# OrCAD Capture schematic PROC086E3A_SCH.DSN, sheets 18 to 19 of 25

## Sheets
18 21. JAMR3 INTERFACE: size C; title: JAMR3 INTERFACE
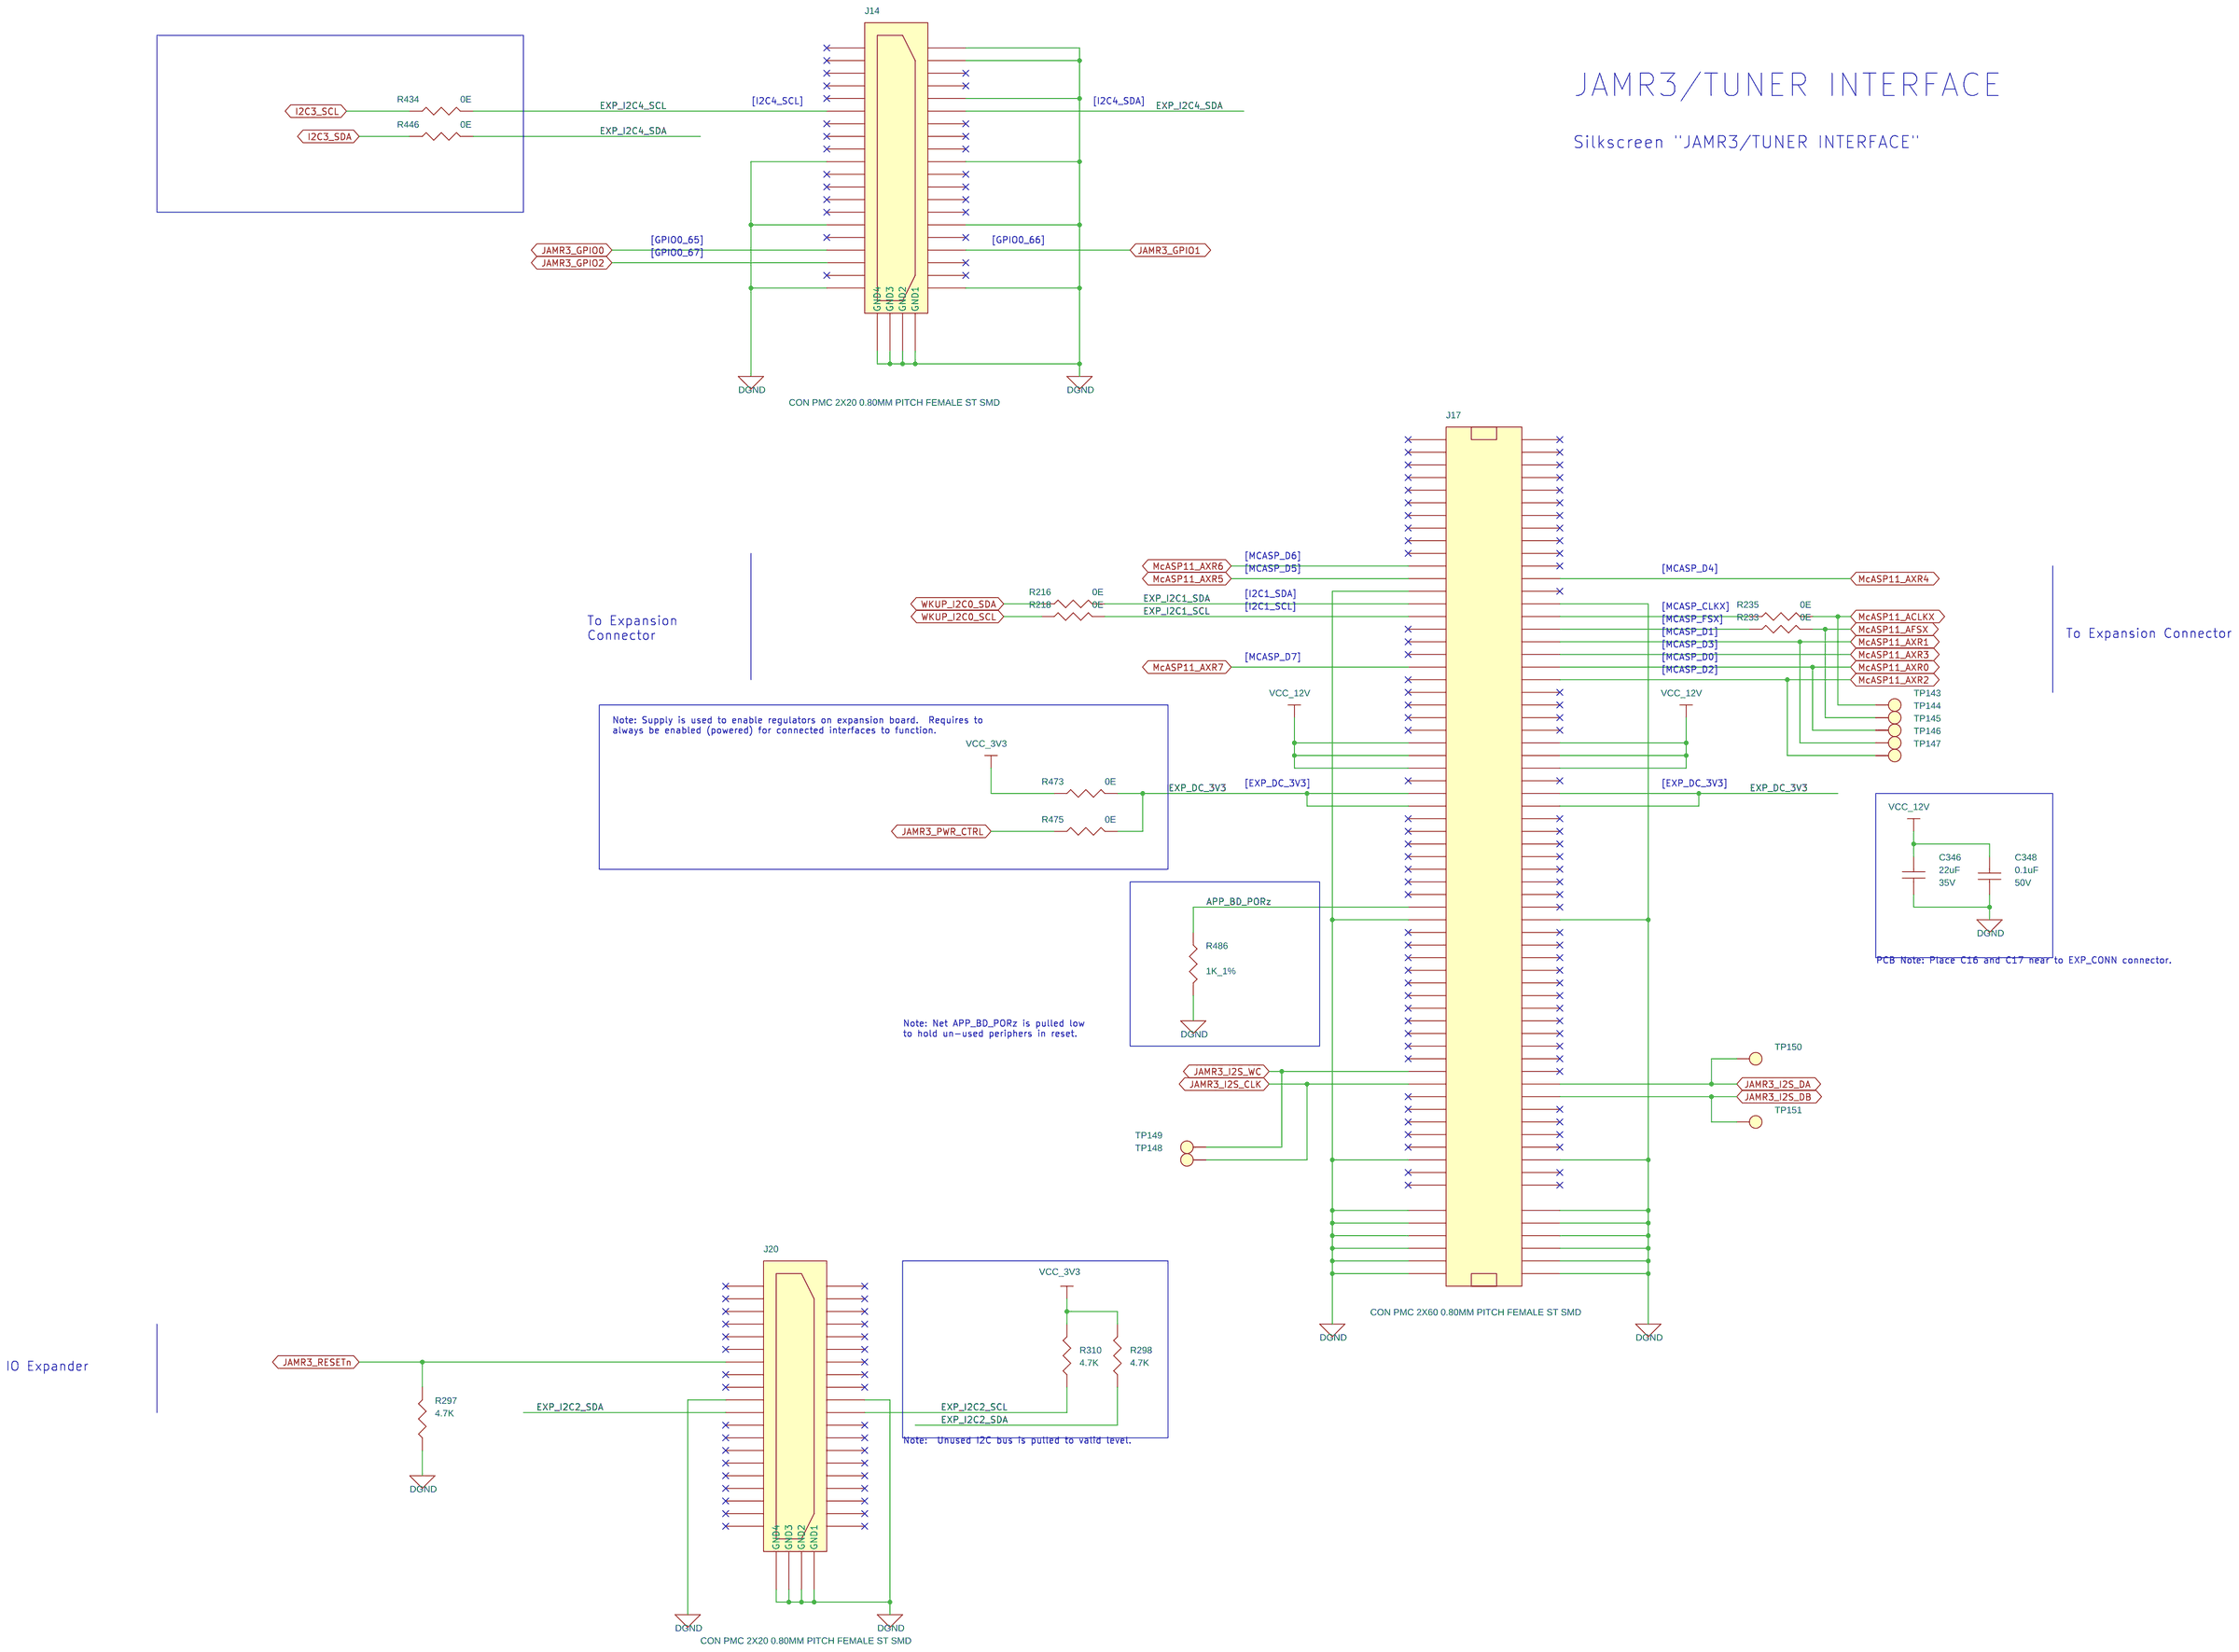
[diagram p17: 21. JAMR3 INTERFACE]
19 22. DIR INTERFACE: size C; title: DIR INTERFACE
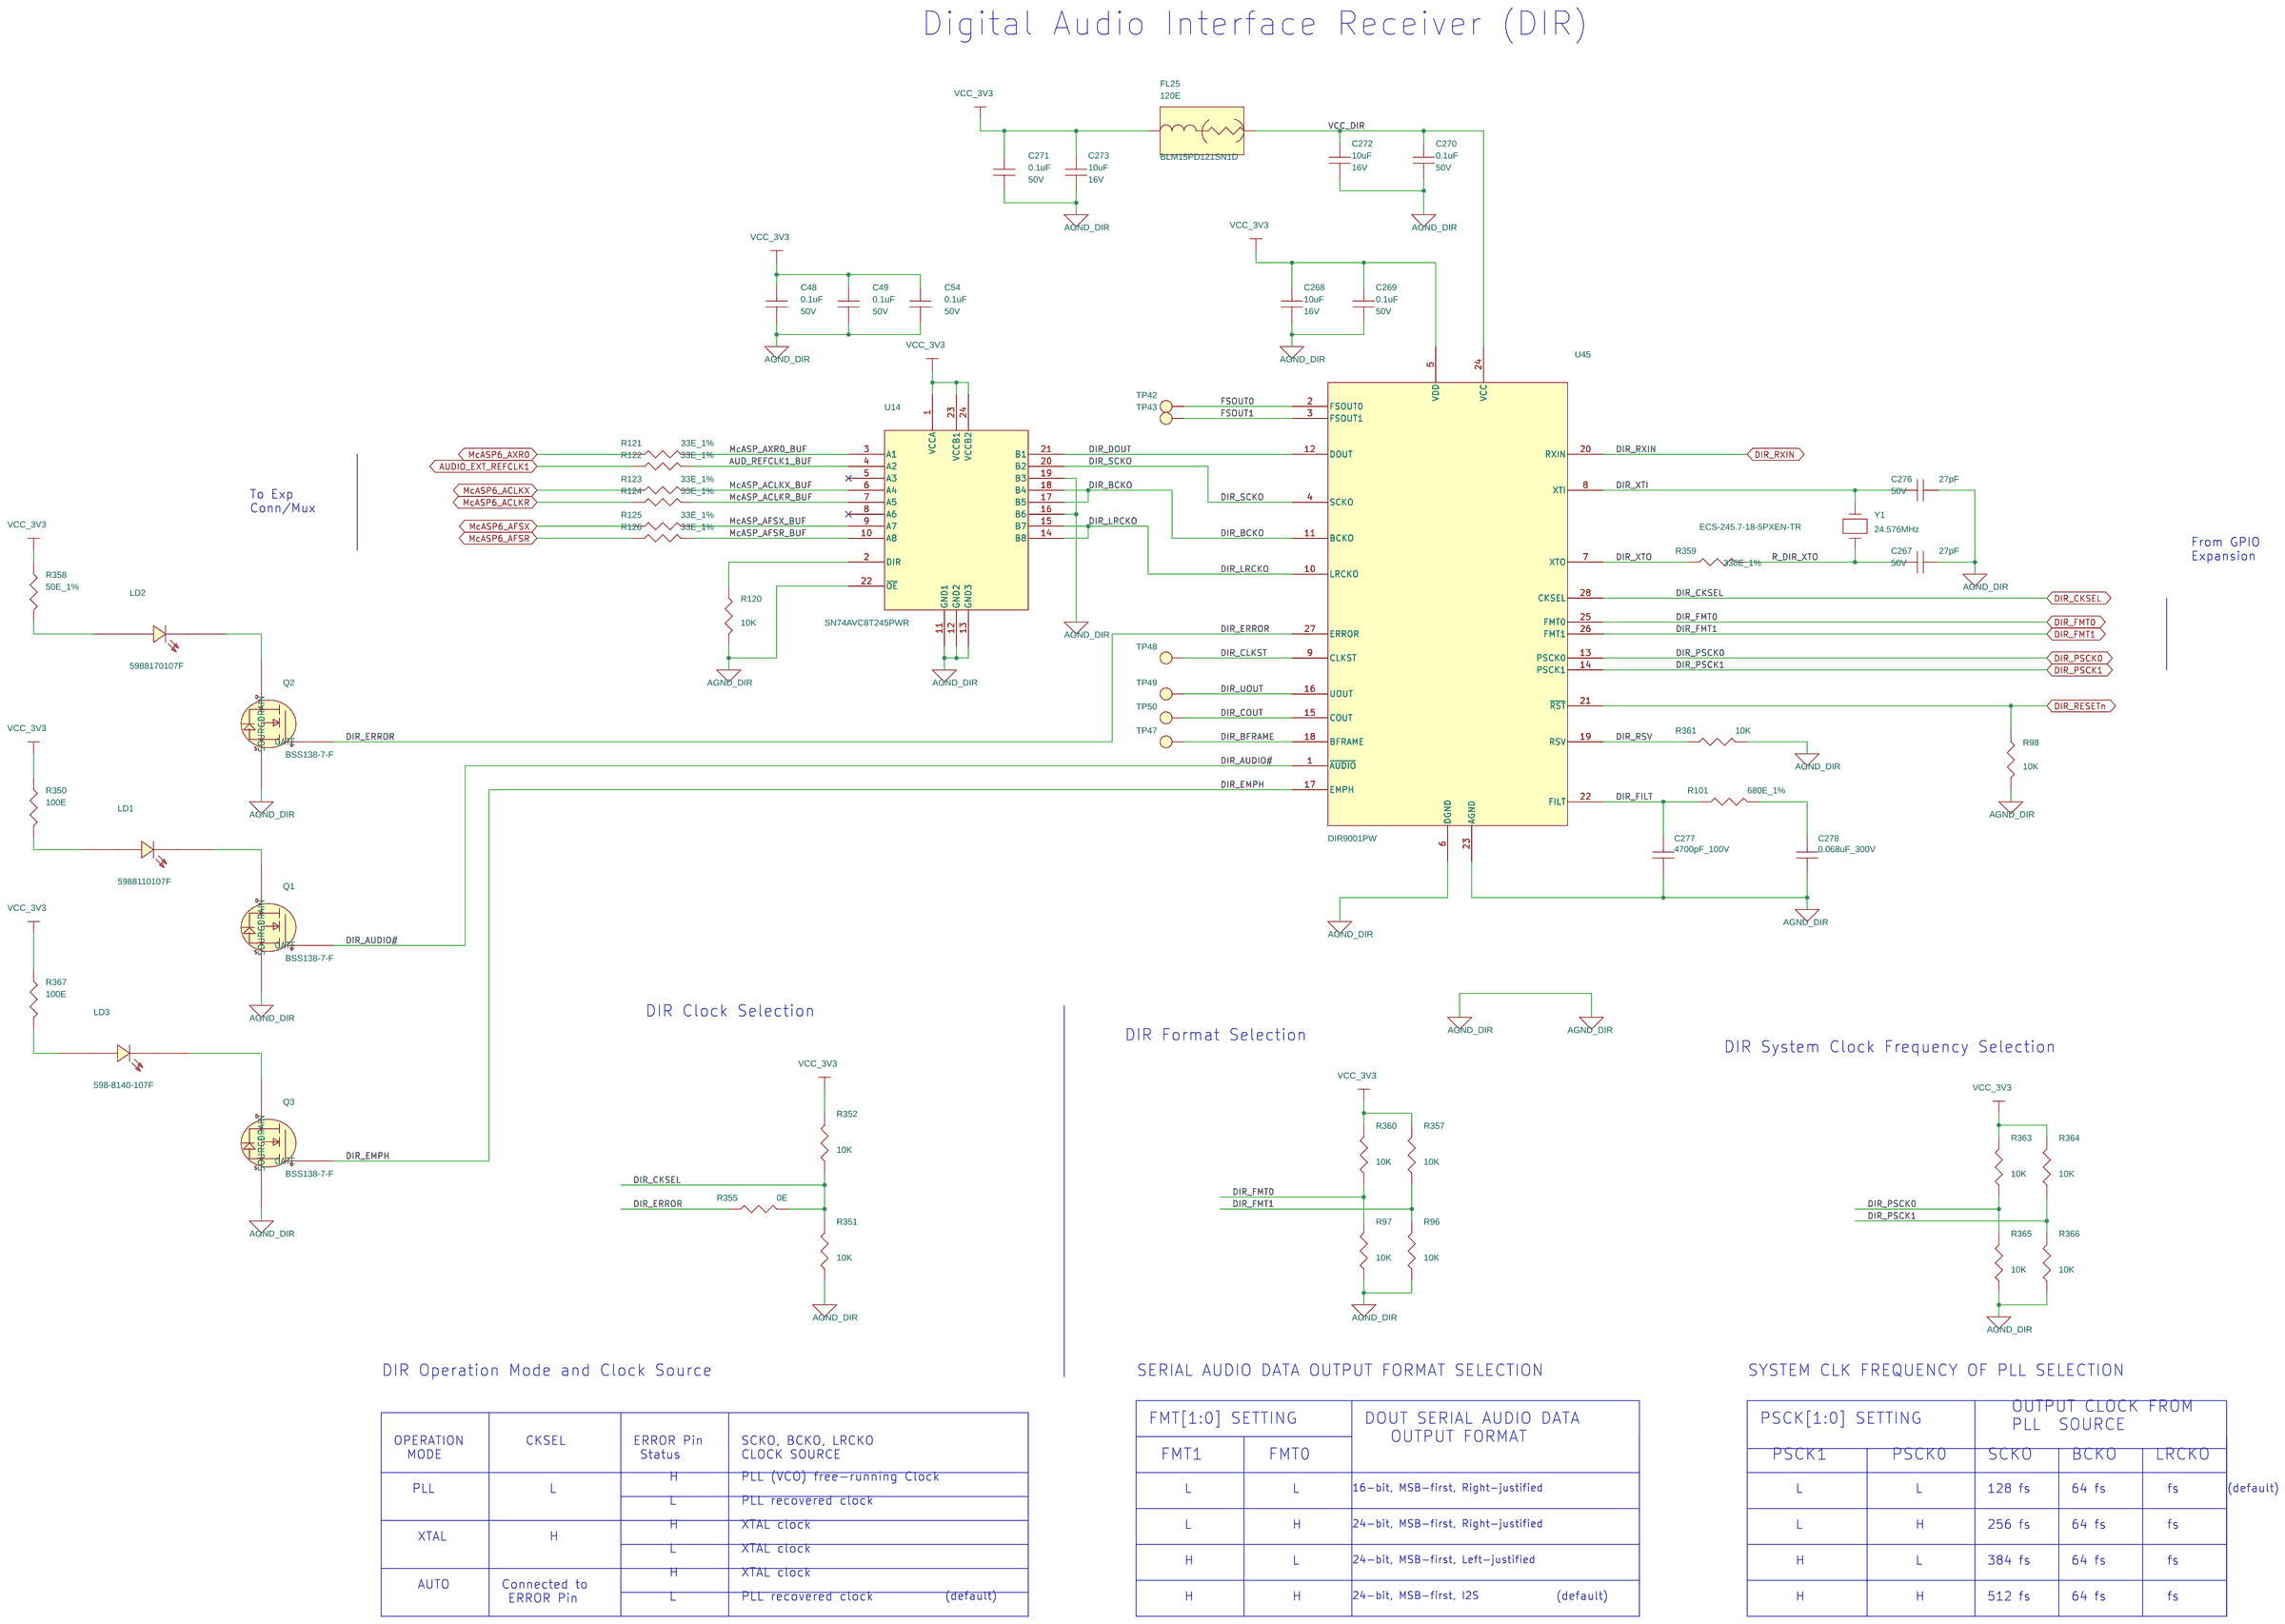
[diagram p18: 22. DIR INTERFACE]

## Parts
sheet 21. JAMR3 INTERFACE
C346  22uF  [CAP1206_2]
C348  0.1uF  [CAP0402_0-75]
J14  CON_PMC_2X20_F  [CON_PMC2X20_QSE-020-01-D-A_S_S_S_3-4]
J17  CON_PMC_2X60_F  [CON_PMC2X60_QSE-060-01-D-A_S_S_S_3-4]
J20  CON_PMC_2X20_F  [CON_PMC2X20_QSE-020-01-D-A_S_S_S_3-4]
R216  0E  [RES0402_0-5]
R218  0E  [RES0402_0-5]
R233  0E  [RES0402_0-5]
R235  0E  [RES0402_0-5]
R297  4.7K  [RES0402_0-5]
R298  4.7K  [RES0402_0-5]
R310  4.7K  [RES0402_0-5]
R434  0E  [RES0402_0-5]
R446  0E  [RES0402_0-5]
R473  0E  [RES0402_0-5]
R475  0E  [RES0402_0-5]
R486  1K_1%  [RES0402_0-5]
TP143  TP20_SMD  [TP20_SMD]
TP144  TP20_SMD  [TP20_SMD]
TP145  TP20_SMD  [TP20_SMD]
TP146  TP20_SMD  [TP20_SMD]
TP147  TP20_SMD  [TP20_SMD]
TP148  TP20_SMD  [TP20_SMD]
TP149  TP20_SMD  [TP20_SMD]
TP150  TP20_SMD  [TP20_SMD]
TP151  TP20_SMD  [TP20_SMD]
sheet 22. DIR INTERFACE
C48  0.1uF  [CAP0402_0-75]
C49  0.1uF  [CAP0402_0-75]
C54  0.1uF  [CAP0402_0-75]
C267  27pF  [CAP0402_0-75]
C268  10uF  [CAP0603_1]
C269  0.1uF  [CAP0402_0-75]
C270  0.1uF  [CAP0402_0-75]
C271  0.1uF  [CAP0402_0-75]
C272  10uF  [CAP0603_1]
C273  10uF  [CAP0603_1]
C276  27pF  [CAP0402_0-75]
C277  4700pF_100V  [CAP_196-85_280X100_TH_6-5]
C278  0.068uF_300V  [CAP_393-7_510X180_TH_10-5]
FL25  120E  [EMIFIL_BLM15A_0402_0-6]
LD1  5988110107F  [LED_0805]
LD2  5988170107F  [LED_0805_0-7]
LD3  598-8140-107F  [LED_0805]
Q1  BSS138-7-F  [SOT23-123_1-1]
Q2  BSS138-7-F  [SOT23-123_1-1]
Q3  BSS138-7-F  [SOT23-123_1-1]
R96  10K  [RES0402_0-5]
R97  10K  [RES0402_0-5]
R98  10K  [RES0402_0-5]
R101  680E_1%  [RES0603_0-75]
R120  10K  [RES0402_0-5]
R121  33E_1%  [RES0402_0-5]
R122  33E_1%  [RES0402_0-5]
R123  33E_1%  [RES0402_0-5]
R124  33E_1%  [RES0402_0-5]
R125  33E_1%  [RES0402_0-5]
R126  33E_1%  [RES0402_0-5]
R350  100E  [RES0402_0-5]
R351  10K  [RES0402_0-5]
R352  10K  [RES0402_0-5]
R355  0E  [RES0402_0-5]
R357  10K  [RES0402_0-5]
R358  50E_1%  [RES0402_0-75]
R359  330E_1%  [RES0402_0-5]
R360  10K  [RES0402_0-5]
R361  10K  [RES0402_0-5]
R363  10K  [RES0402_0-5]
R364  10K  [RES0402_0-5]
R365  10K  [RES0402_0-5]
R366  10K  [RES0402_0-5]
R367  100E  [RES0402_0-5]
TP42  TP40_SMD  [TP40_SMD]
TP43  TP40_SMD  [TP40_SMD]
TP47  TP40_SMD  [TP40_SMD]
TP48  TP40_SMD  [TP40_SMD]
TP49  TP40_SMD  [TP40_SMD]
TP50  TP40_SMD  [TP40_SMD]
U14  SN74AVC8T245PWR  [TSSOP24_25-59_315X180_1-2]
U45  DIR9001PW  [TSSOP28_25-59_390X180_1-2]
Y1  24.576MHz  [XTAL_CSM-7X_450X190_SMD_4-3]

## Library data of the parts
C346 = CAP: CAP CERAMIC 22uF 35V 20% X5R 1206; Chkd/date: MANIRAJA/130318; Crtd /date: MANIRAJA/130318; Custom_Duty: 15%; Customs_HS_Code: 85322990; Distributor_name: DIGIKEY; Distributor_part_number: 445-8045-1-ND; Footprint Path: Y:\MIS_DATABASE\Library\ALTIUM_TOOL\PCB_FOOTPRINTS\Altium_Footprint_Lib.PcbLib; Height: 1.80MM; Library Path: Y:\MIS_DATABASE\Library\ALTIUM_TOOL\SCHEMATICS_PARTS\MS_DISCRETE_Library.schlib; Mfr_name: TDK CORPORATION; Mfr_part_number: C3216X5R1V226M160AC; Mistral Part No: 120018030003-R; Package: 1206; Part_type: CAPACITORS\CERAMIC; Project: TI_SVB_MAXWELL_VPS; RoHS: RoHS; Temperature: -55°C+85°C; Tolerance: 20%; Voltage: 35V; Wattage: NA; Weight: 16.2mg; Datasheet: Y:\MIS_DATABASE\DATASHEETS\CAPACITORS\C3216X5R1V226M160AC.PDF
C48 C49 C54 C269-C271 C348 = CAP: CAP CERAMIC 0.1uF 50V 10% X7R 0402; Chkd/date: VASANTHA/281216; Crtd /date: CHAITHANYA/051011; Custom_Duty: 15%; Customs_HS_Code: 85322990; Distributor_name: DIGIKEY; Distributor_part_number: 445-173610-1-ND; Footprint Path: Y:\MIS_DATABASE\Library\ALTIUM_TOOL\PCB_FOOTPRINTS\Altium_Footprint_Lib.PcbLib; Height: 0.60MM; Library Path: Y:\MIS_DATABASE\Library\ALTIUM_TOOL\SCHEMATICS_PARTS\MS_DISCRETE_Library.schlib; Mfr_name: TDK CORPORATION; Mfr_part_number: C1005X7R1H104K050BE; Mistral Part No: 120011100014-R; Package: 0402; Part_type: CAPACITORS\CERAMIC; Project: VP-4000-BASE-BOARD; RoHS: RoHS; Temperature: -55°C+125°C; Tolerance: 10%; Voltage: 50V; Wattage: NA; Weight: 0.65mg; Datasheet: Y:\MIS_DATABASE\DATASHEETS\CAPACITORS\TDK_C-SER_FEB19.PDF
J14 J20 = CON_PMC_20X2_F: CON PMC 2X20 0.80MM PITCH FEMALE ST SMD; Chkd/date: MANIRAJA/190718; Crtd /date: ALVY/190718; Custom_Duty: 24%; Customs_HS_Code: 85369090; Distributor_name: DIGIKEY; Distributor_part_number: SAM10642-ND; Footprint Path: Y:\MIS_DATABASE\Library\ALTIUM_TOOL\PCB_FOOTPRINTS\Altium_Footprint_Lib.PcbLib; Height: 3.33MM; Library Path: Y:\MIS_DATABASE\Library\ALTIUM_TOOL\SCHEMATICS_PARTS\MS_CONNECTOR_Library.schlib; Mfr_name: SAMTEC; Mfr_part_number: QSE-020-01-L-D-A-K; Mistral Part No: 150018070032-R; Package: SMD; Part_type: CONNECTOR\PMC; Project: TI_J7ES_EVM_TUNER_EXP; RoHS: RoHS; Temperature: -55°C+125°C; Tolerance: NA; Voltage: NA; Wattage: NA; Weight: NA; Datasheet: Y:\MIS_DATABASE\DATASHEETS\CONNECTORS\QSE3.PDF
J17 = CON_PMC_60X2_F_QSH-060: CON PMC 2X60 0.80MM PITCH FEMALE ST SMD; Chkd/date: MANIRAJA/190718; Crtd /date: MAZHAR/131009; Custom_Duty: 24%; Customs_HS_Code: 85369090; Distributor_name: DIGIKEY; Distributor_part_number: SAM10646-ND; Footprint Path: Y:\MIS_DATABASE\Library\ALTIUM_TOOL\PCB_FOOTPRINTS\Altium_Footprint_Lib.PcbLib; Height: 3.33MM; Library Path: Y:\MIS_DATABASE\Library\ALTIUM_TOOL\SCHEMATICS_PARTS\MS_CONNECTOR_Library.schlib; Mfr_name: SAMTEC; Mfr_part_number: QSE-060-01-L-D-A; Mistral Part No: 150009100010-R; Package: SMD; Part_type: CONNECTOR\PMC; Project: NPOL_FPS; RoHS: RoHS; Temperature: -55°C+125°C; Tolerance: NA; Voltage: NA; Wattage: NA; Weight: NA; Datasheet: Y:\MIS_DATABASE\DATASHEETS\CONNECTORS\QSE3.PDF
R216 R218 R233 R235 R355 R434 R446 R473 = RESISTOR: RES 0E 1/10W JUMPER 0402; Chkd/date: VASANTHA/061216; Crtd /date: NAVEED/201014; Custom_Duty: 15%; Customs_HS_Code: 85332119; Distributor_name: DIGIKEY; Distributor_part_number: P0.0JCT-ND; Footprint Path: Y:\MIS_DATABASE\Library\ALTIUM_TOOL\PCB_FOOTPRINTS\Altium_Footprint_Lib.PcbLib; Height: 0.40MM; IBISSP_MODLES: VALUE REPEATING 2 TIME; Library Path: Y:\MIS_DATABASE\Library\ALTIUM_TOOL\SCHEMATICS_PARTS\MS_DISCRETE_Library.schlib; Mfr_name: PANASONIC-ECG; Mfr_part_number: ERJ-2GE0R00X; Mistral Part No: 110018030052-R; Package: 0402; Part_type: RESISTORS\FIXED; Project: AEGIS POM; RoHS: RoHS; Temperature: -55°C+155°C; Tolerance: NA; Voltage: NA; Wattage: 1/10W; Weight: 0.8mg; Datasheet: Y:\MIS_DATABASE\DATASHEETS\RESISTORS\PAN-ERJSER_NOV17.PDF
R297 R298 R310 = RESISTOR: RES 4.7K 1/16W 5% 0402; Chkd/date: VASANTHA/281216; Crtd /date: BAVISH/010611; Custom_Duty: 15%; Customs_HS_Code: 85332119; Distributor_name: DIGIKEY; Distributor_part_number: 541-4.7KJCT-ND; Footprint Path: Y:\MIS_DATABASE\Library\ALTIUM_TOOL\PCB_FOOTPRINTS\Altium_Footprint_Lib.PcbLib; Height: 0.40MM; Library Path: Y:\MIS_DATABASE\Library\ALTIUM_TOOL\SCHEMATICS_PARTS\MS_DISCRETE_Library.schlib; Mfr_name: VISHAY; Mfr_part_number: CRCW04024K70JNED; Mistral Part No: 110011060001-R; Package: 0402; Part_type: RESISTORS\FIXED; Project: AM4515_EVM_LCD; RoHS: RoHS; Temperature: -55°C+155°C; Tolerance: 5%; Voltage: NA; Wattage: 1/16W; Weight: 0.65mg; Datasheet: Y:\MIS_DATABASE\DATASHEETS\RESISTORS\CRCW0603.PDF
R475 = RESISTOR: RES 0E 1/10W JUMPER 0402; Assembly_Instruction: DNI; Chkd/date: VASANTHA/061216; Crtd /date: NAVEED/201014; Custom_Duty: 15%; Customs_HS_Code: 85332119; Distributor_name: DIGIKEY; Distributor_part_number: P0.0JCT-ND; Footprint Path: Y:\MIS_DATABASE\Library\ALTIUM_TOOL\PCB_FOOTPRINTS\Altium_Footprint_Lib.PcbLib; Height: 0.40MM; IBISSP_MODLES: VALUE REPEATING 2 TIME; Library Path: Y:\MIS_DATABASE\Library\ALTIUM_TOOL\SCHEMATICS_PARTS\MS_DISCRETE_Library.schlib; Mfr_name: PANASONIC-ECG; Mfr_part_number: ERJ-2GE0R00X; Mistral Part No: 110018030052-R; Package: 0402; Part_type: RESISTORS\FIXED; Project: AEGIS POM; RoHS: RoHS; Temperature: -55°C+155°C; Tolerance: NA; Voltage: NA; Wattage: 1/10W; Weight: 0.8mg; Datasheet: Y:\MIS_DATABASE\DATASHEETS\RESISTORS\PAN-ERJSER_NOV17.PDF
R486 = RESISTOR: RES 1K 1/10W 1% 0402; Chkd/date: VASANTHA/281216; Crtd /date: MAZHAR/150506; Custom_Duty: 15%; Customs_HS_Code: 85332119; Distributor_name: DIGIKEY; Distributor_part_number: P1.00KLCT-ND; Footprint Path: Y:\MIS_DATABASE\Library\ALTIUM_TOOL\PCB_FOOTPRINTS\Altium_Footprint_Lib.PcbLib; Height: 0.40MM; Library Path: Y:\MIS_DATABASE\Library\ALTIUM_TOOL\SCHEMATICS_PARTS\MS_DISCRETE_Library.schlib; Mfr_name: PANASONIC-ECG; Mfr_part_number: ERJ-2RKF1001X; Mistral Part No: 110009030411-R; Package: 0402; Part_type: RESISTORS\FIXED; Project: VOCERA; RoHS: RoHS; Temperature: -55°C+155°C; Tolerance: 1%; Voltage: NA; Wattage: 1/10W; Weight: 0.8mg; Datasheet: Y:\MIS_DATABASE\DATASHEETS\RESISTORS\PAN-ERJSER_NOV17.PDF
TP143-TP151 = TESTPOINT: TESTPOINT CIR 20 SMD; Chkd/date: SHREESHAIL/171006; Crtd /date: MAZHAR/171006; Custom_Duty: NA; Customs_HS_Code: NA; Distributor_name: NA; Distributor_part_number: NA; Footprint Path: Y:\MIS_DATABASE\Library\ALTIUM_TOOL\PCB_FOOTPRINTS\Altium_Footprint_Lib.PcbLib; Height: NA; Library Path: Y:\MIS_DATABASE\Library\ALTIUM_TOOL\SCHEMATICS_PARTS\MS_DISCRETE_Library.schlib; MECHANICAL 3D STEP FILE: NA; Mfr_name: LOCAL; Mistral Part No: NA; Package: SMD; Project: BT MODULE_CSRBC04; RoHS: NA; Temperature: NA; Tolerance: NA; Voltage: NA; Wattage: NA; Weight: NA; Datasheet: NA
C267 C276 = CAP: CAP CERAMIC 27pF 50V 5% C0G(NP0) 0402; Chkd/date: MANIRAJA/130917; Crtd /date: MANIRAJA/130917; Custom_Duty: 15%; Customs_HS_Code: 85322990; Distributor_name: DIGIKEY; Distributor_part_number: 478-1075-1-ND; Footprint Path: Y:\MIS_DATABASE\Library\ALTIUM_TOOL\PCB_FOOTPRINTS\Altium_Footprint_Lib.PcbLib; Height: 0.56MM; Library Path: Y:\MIS_DATABASE\Library\ALTIUM_TOOL\SCHEMATICS_PARTS\MS_DISCRETE_Library.schlib; Mfr_name: AVX CORPORATION; Mfr_part_number: 04025A270JAT2A; Mistral Part No: 120014100024-R; Package: 0402; Part_type: CAPACITORS\CERAMIC; Project: TI_SVB_MAXWELL_DUT; RoHS: RoHS; Temperature: -55°C+125°C; Tolerance: 5%; Voltage: 50V; Wattage: NA; Weight: 0.65mg; Datasheet: Y:\MIS_DATABASE\DATASHEETS\CAPACITORS\AVX_MLC.PDF
C268 C272 C273 = CAP: CAP CERAMIC 10uF 16V 20% X6S 0603; Chkd/date: VASANTHA/170117; Crtd /date: VASANTHA/170117; Custom_Duty: 15%; Customs_HS_Code: 85322990; Distributor_name: DIGIKEY; Distributor_part_number: 490-7198-1-ND; Footprint Path: Y:\MIS_DATABASE\Library\ALTIUM_TOOL\PCB_FOOTPRINTS\Altium_Footprint_Lib.PcbLib; Height: 0.90MM; Library Path: Y:\MIS_DATABASE\Library\ALTIUM_TOOL\SCHEMATICS_PARTS\MS_DISCRETE_Library.schlib; Mfr_name: MURATA; Mfr_part_number: GRM188C81C106MA73D; Mistral Part No: 120017010004-R; Package: 0603; Part_type: CAPACITORS\CERAMIC; Project: TRMM_SMART-M_PS; RoHS: RoHS; Temperature: -55°C+105°C; Tolerance: 20%; Voltage: 16V; Wattage: NA; Weight: 6.3mg; Datasheet: Y:\MIS_DATABASE\DATASHEETS\CAPACITORS\MURATA-GXX-SER_NOV17.PDF
C277 = CAP: CAP POLYPROPYLENE 4700pF 100V 5% TH; Chkd/date: NAVEED/270315; Crtd /date: JEBRAN/260215; Custom_Duty: 15%; Customs_HS_Code: 85322990; Distributor_name: MOUSER; Distributor_part_number: 80-PHE426DJ4470JR05; Footprint Path: Y:\MIS_DATABASE\Library\ALTIUM_TOOL\PCB_FOOTPRINTS\Altium_Footprint_Lib.PcbLib; Height: 6.50MM; Library Path: Y:\MIS_DATABASE\Library\ALTIUM_TOOL\SCHEMATICS_PARTS\MS_DISCRETE_Library.schlib; Mfr_name: KEMET; Mfr_part_number: PHE426DJ4470JR05; Mistral Part No: 120015020004-R; Package: THRU-HOLE; Part_type: CAPACITORS\POLYPROPYLENE; Project: GALILEO_DAUGHTER_CARD; RoHS: RoHS; Temperature: -55°C+105°C; Tolerance: 5%; Voltage: 100V; Wattage: NA; Weight: 172.44mg; Datasheet: Y:\MIS_DATABASE\DATASHEETS\CAPACITORS\PHE426-SERIES.PDF
C278 = CAP: CAP POLYPROPYLENE 0.068uF 300V 5% TH; Chkd/date: NAVEED/260315; Crtd /date: JEBRAN/250315; Custom_Duty: 15%; Customs_HS_Code: 85322990; Distributor_name: MOUSER; Distributor_part_number: 80-PHE426JA5680JR05; Footprint Path: Y:\MIS_DATABASE\Library\ALTIUM_TOOL\PCB_FOOTPRINTS\Altium_Footprint_Lib.PcbLib; Height: 10.50MM; Library Path: Y:\MIS_DATABASE\Library\ALTIUM_TOOL\SCHEMATICS_PARTS\MS_DISCRETE_Library.schlib; Mfr_name: KEMET; Mfr_part_number: PHE426JA5680JR05; Mistral Part No: 120015030004-R; Package: THRU-HOLE; Part_type: CAPACITORS\POLYPROPYLENE; Project: GALILEO_DAUGHTER_CARD; RoHS: RoHS; Temperature: -55°C+105°C; Tolerance: 5%; Voltage: 300V; Wattage: NA; Weight: NA; Datasheet: Y:\MIS_DATABASE\DATASHEETS\CAPACITORS\PHE426-SERIES.PDF
FL25 = EMIFILTER_IND: IND FERRITE BEAD CHIP 120E 1.3A 0402; Chkd/date: VASANTHA/010117; Crtd /date: CHAITHANYA/150312; Custom_Duty: 24%; Customs_HS_Code: 85437099; Distributor_name: DIGIKEY; Distributor_part_number: 490-5203-1-ND; Footprint Path: Y:\MIS_DATABASE\Library\ALTIUM_TOOL\PCB_FOOTPRINTS\Altium_Footprint_Lib.PcbLib; Height: 0.55MM; Library Path: Y:\MIS_DATABASE\Library\ALTIUM_TOOL\SCHEMATICS_PARTS\MS_FILTER_Library.schlib; Mfr_name: MURATA; Mfr_part_number: BLM15PD121SN1D; Mistral Part No: 130012030043-R; Package: 0402; Part_type: FILTER; Project: GEN_3-8; RoHS: RoHS; Temperature: -55°C+125°C; Tolerance: 25%; Voltage: NA; Wattage: NA; Weight: 0.65mg; Datasheet: Y:\MIS_DATABASE\DATASHEETS\DISCRETES\INDUCTORS\BLM15X-SER.PDF
LD1 = LED_598-8170-107F: LED ALINGAP RED CLEAR 0805 SMD; Chkd/date: BALACHANDAR/160514; Crtd /date: SARANYA/070514; Custom_Duty: 24%; Customs_HS_Code: 85437099; Distributor_name: DIGIKEY; Distributor_part_number: 350-2038-1-ND; Footprint Path: Y:\MIS_DATABASE\Library\ALTIUM_TOOL\PCB_FOOTPRINTS\Altium_Footprint_Lib.PcbLib; Height: 0.70MM; Mfr_name: DIALIGHT; Mistral Part No: 130014050069-R; Package: 0805; Part_type: OPTO\LED; Project: AEGIS GP BETA2; RoHS: RoHS; Temperature: NA; Tolerance: NA; Voltage: NA; Wattage: NA; Weight: NA; Datasheet: Y:\MIS_DATABASE\DATASHEETS\DISCRETES\LEDS\598-SER.PDF
LD2 = LED_598-8170-107F: LED ALINGAP GREEN CLEAR 0805; Chkd/date: MANIRAJA/230817; Crtd /date: SARANYA/070514; Custom_Duty: 24%; Customs_HS_Code: 85437099; Distributor_name: DIGIKEY; Distributor_part_number: 350-2044-1-ND; Footprint Path: Y:\MIS_DATABASE\Library\ALTIUM_TOOL\PCB_FOOTPRINTS\Altium_Footprint_Lib.PcbLib; Height: 0.70MM; Mfr_name: DIALIGHT; Mistral Part No: 130014050065-R; Package: 0805; Part_type: OPTO\LED; Project: AEGIS GP BETA2; RoHS: RoHS; Temperature: -30°C+85°C; Tolerance: NA; Voltage: NA; Wattage: NA; Weight: NA; Datasheet: Y:\MIS_DATABASE\DATASHEETS\DISCRETES\LEDS\598-SER.PDF
LD3 = LED_598-8170-107F: LED ALINGAP YELLOW CLEAR 0805 SMD; Chkd/date: BALACHANDAR/160514; Crtd /date: SARANYA/070514; Custom_Duty: 24%; Customs_HS_Code: 85437099; Distributor_name: DIGIKEY; Distributor_part_number: 350-2041-1-ND; Height: 0.70MM; Mfr_name: DIALIGHT; Mistral Part No: 130014050066-R; Package: 0805; Part_type: OPTO\LED; Project: AEGIS GP BETA2; RoHS: RoHS; Temperature: NA; Tolerance: NA; Voltage: NA; Wattage: NA; Weight: NA; Datasheet: Y:\MIS_DATABASE\DATASHEETS\DISCRETES\LEDS\598-SER.PDF
Q1-Q3 = MOSFET_2N7002_SOT23: IC MOSFET N-CHANNEL 50V 200mA SOT23-123; Chkd/date: MANIRAJA/190618; Crtd /date: USMAN/240709; Custom_Duty: 15%; Customs_HS_Code: 85423100; Distributor_name: DIGIKEY; Distributor_part_number: BSS138-FDICT-ND; Footprint Path: Y:\MIS_DATABASE\Library\ALTIUM_TOOL\PCB_FOOTPRINTS\Altium_Footprint_Lib.PcbLib; Height: 1.10MM; Library Path: Y:\MIS_DATABASE\Library\ALTIUM_TOOL\SCHEMATICS_PARTS\MS_MOSFET_Library.schlib; Mfr_name: DIODES INC; Mistral Part No: 142009070019-R; Package: SOT23-123; Part_type: ICS\POWER\MOSFET; Project: KHAN_MAIN; RoHS: RoHS; Temperature: -55°C+150°C; Tolerance: NA; Voltage: 50V; Wattage: 300mW; Weight: 8mg; Datasheet: Y:\MIS_DATABASE\DATASHEETS\DISCRETES\TRANSISTORS_FETS\BSS138.PDF
R96 R97 R351 R363 R364 = RESISTOR: RES 10K 1/16W 5% 0402; Assembly_Instruction: DNI; Chkd/date: VASANTHA/061216; Crtd /date: MAZHAR/230805; Custom_Duty: 15%; Customs_HS_Code: 85332119; Distributor_name: DIGIKEY; Distributor_part_number: 311-10KJRCT-ND; Footprint Path: Y:\MIS_DATABASE\Library\ALTIUM_TOOL\PCB_FOOTPRINTS\Altium_Footprint_Lib.PcbLib; Height: 0.40MM; Library Path: Y:\MIS_DATABASE\Library\ALTIUM_TOOL\SCHEMATICS_PARTS\MS_DISCRETE_Library.schlib; Mfr_name: YAGEO AMERICA; Mfr_part_number: RC0402JR-0710KL; Mistral Part No: 110011060021-R; Package: 0402; Part_type: RESISTORS\FIXED; Project: HSE; RoHS: RoHS; Temperature: -55°C+155°C; Tolerance: 5%; Voltage: NA; Wattage: 1/16W; Weight: 0.65mg; Datasheet: Y:\MIS_DATABASE\DATASHEETS\RESISTORS\RCXXXXL-SER_MAR18.PDF
R98 R120 R352 R357 R360 R361 R365 R366 = RESISTOR: RES 10K 1/16W 5% 0402; Chkd/date: VASANTHA/061216; Crtd /date: MAZHAR/230805; Custom_Duty: 15%; Customs_HS_Code: 85332119; Distributor_name: DIGIKEY; Distributor_part_number: 311-10KJRCT-ND; Footprint Path: Y:\MIS_DATABASE\Library\ALTIUM_TOOL\PCB_FOOTPRINTS\Altium_Footprint_Lib.PcbLib; Height: 0.40MM; Library Path: Y:\MIS_DATABASE\Library\ALTIUM_TOOL\SCHEMATICS_PARTS\MS_DISCRETE_Library.schlib; Mfr_name: YAGEO AMERICA; Mfr_part_number: RC0402JR-0710KL; Mistral Part No: 110011060021-R; Package: 0402; Part_type: RESISTORS\FIXED; Project: HSE; RoHS: RoHS; Temperature: -55°C+155°C; Tolerance: 5%; Voltage: NA; Wattage: 1/16W; Weight: 0.65mg; Datasheet: Y:\MIS_DATABASE\DATASHEETS\RESISTORS\RCXXXXL-SER_MAR18.PDF
R101 = RESISTOR: RES 680E 1/10W 1% 0603; Chkd/date: NAVEED/201014; Crtd /date: VASANTHA/110914; Custom_Duty: 15%; Customs_HS_Code: 85332119; Distributor_name: DIGIKEY; Distributor_part_number: 311-680HRCT-ND; Footprint Path: Y:\MIS_DATABASE\Library\ALTIUM_TOOL\PCB_FOOTPRINTS\Altium_Footprint_Lib.PcbLib; Height: 0.55MM; Library Path: Y:\MIS_DATABASE\Library\ALTIUM_TOOL\SCHEMATICS_PARTS\MS_DISCRETE_Library.schlib; Mfr_name: YAGEO AMERICA; Mfr_part_number: RC0603FR-07680RL; Mistral Part No: 110014090002-R; Package: 0603; Part_type: RESISTORS\FIXED; Project: PDDS; RoHS: RoHS; Temperature: -55°C+155°C; Tolerance: 1%; Voltage: NA; Wattage: 1/10W; Weight: 2mg; Datasheet: Y:\MIS_DATABASE\DATASHEETS\RESISTORS\RCXXXXL-SER_MAR18.PDF
R121-R126 = RESISTOR: RES 33E 1/10W 1% 0402; Chkd/date: VASANTHA/061216; Crtd /date: JEBRAN/171114; Custom_Duty: 15%; Customs_HS_Code: 85332119; Distributor_name: DIGIKEY; Distributor_part_number: P33.0LCT-ND; Footprint Path: Y:\MIS_DATABASE\Library\ALTIUM_TOOL\PCB_FOOTPRINTS\Altium_Footprint_Lib.PcbLib; Height: 0.40MM; Library Path: Y:\MIS_DATABASE\Library\ALTIUM_TOOL\SCHEMATICS_PARTS\MS_DISCRETE_Library.schlib; Mfr_name: PANASONIC-ECG; Mfr_part_number: ERJ-2RKF33R0X; Mistral Part No: 110014110006-R; Package: 0402; Part_type: RESISTORS\FIXED; Project: ZK BIOMETRIC; RoHS: RoHS; Temperature: -55°C+155°C; Tolerance: 1%; Voltage: NA; Wattage: 1/10W; Weight: 0.8mg; Datasheet: Y:\MIS_DATABASE\DATASHEETS\RESISTORS\PAN-ERJSER_NOV17.PDF
R350 R367 = RESISTOR: RES 100E 1/16W 5% 0402; Chkd/date: MANIRAJA/230817; Crtd /date: MANIRAJA/230817; Custom_Duty: 15%; Customs_HS_Code: 85332119; Distributor_name: DIGIKEY; Distributor_part_number: 541-100JCT-ND; Footprint Path: Y:\MIS_DATABASE\Library\ALTIUM_TOOL\PCB_FOOTPRINTS\Altium_Footprint_Lib.PcbLib; Height: 0.40MM; Library Path: Y:\MIS_DATABASE\Library\ALTIUM_TOOL\SCHEMATICS_PARTS\MS_DISCRETE_Library.schlib; Mfr_name: VISHAY; Mfr_part_number: CRCW0402100RJNED; Mistral Part No: 110014060039-R; Package: 0402; Part_type: RESISTORS\FIXED; Project: TI_MAXIE_CPB; RoHS: RoHS; Temperature: -55°C+155°C; Tolerance: 5%; Voltage: NA; Wattage: 1/16W; Weight: 0.65mg; Datasheet: Y:\MIS_DATABASE\DATASHEETS\RESISTORS\CRCW0603.PDF
R358 = RESISTOR: RES 50E 1/8W 1% 0402; Chkd/date: MANIRAJA/160218; Crtd /date: ALVY/140218; Custom_Duty: 15%; Customs_HS_Code: 85332119; Distributor_name: DIGIKEY; Distributor_part_number: 1284-1326-1-ND; Footprint Path: Y:\MIS_DATABASE\Library\ALTIUM_TOOL\PCB_FOOTPRINTS\Altium_Footprint_Lib.PcbLib; Height: 0.60MM; Library Path: Y:\MIS_DATABASE\Library\ALTIUM_TOOL\SCHEMATICS_PARTS\MS_DISCRETE_Library.schlib; Mfr_name: ATC; Mfr_part_number: 504L50R0FTNCFT; Mistral Part No: 110018020017-R; Package: 0402; Part_type: RESISTORS\FIXED; Project: TI_SVB_MAXWELL_SPM; RoHS: RoHS; Temperature: -40°C+125°C; Tolerance: 1%; Voltage: NA; Wattage: 1/8W; Weight: 0.65mg; Datasheet: Y:\MIS_DATABASE\DATASHEETS\RESISTORS\ATC504L-SERIES.PDF
R359 = RESISTOR: RES 330E 1/16W 1% 0402; Chkd/date: VASANTHA/201216; Crtd /date: GEETHA/090606; Custom_Duty: 15%; Customs_HS_Code: 85332119; Distributor_name: DIGIKEY; Distributor_part_number: 311-330LRCT-ND; Footprint Path: Y:\MIS_DATABASE\Library\ALTIUM_TOOL\PCB_FOOTPRINTS\Altium_Footprint_Lib.PcbLib; Height: 0.40MM; Library Path: Y:\MIS_DATABASE\Library\ALTIUM_TOOL\SCHEMATICS_PARTS\MS_DISCRETE_Library.schlib; Mfr_name: YAGEO AMERICA; Mfr_part_number: RC0402FR-07330RL; Mistral Part No: 110009030691-R; Package: 0402; Part_type: RESISTORS\FIXED; Project: PNAV; RoHS: RoHS; Temperature: -55°C+155°C; Tolerance: 1%; Voltage: NA; Wattage: 1/16W; Weight: 0.65mg; Datasheet: Y:\MIS_DATABASE\DATASHEETS\RESISTORS\RCXXXXL-SER_MAR18.PDF
TP42 TP43 TP47-TP50 = TESTPOINT: TESTPOINT CIR 40 SMD; Chkd/date: MAZHAR/190505; Crtd /date: MAZHAR/190505; Distributor_name: NA; Distributor_part_number: NA; Footprint Path: Y:\MIS_DATABASE\Library\ALTIUM_TOOL\PCB_FOOTPRINTS\Altium_Footprint_Lib.PcbLib; Height: NA; Library Path: Y:\MIS_DATABASE\Library\ALTIUM_TOOL\SCHEMATICS_PARTS\MS_DISCRETE_Library.schlib; MECHANICAL 3D STEP FILE: NA; Mfr_name: LOCAL; Mistral Part No: 130009030933; Package: SMD; Project: RAINIER-3; RoHS: NA; Temperature: NA; Tolerance: NA; Voltage: NA; Wattage: NA; Weight: NA; Datasheet: NA
U14 = SN74AVC8T245PWR_TSSOP24: IC 8-BIT DUAL-SUPPLY BUS TRANSCEIVER TSSOP24; Chkd/date: MANIRAJA/040917; Crtd /date: USMAN/040509; Custom_Duty: 15%; Customs_HS_Code: 85423100; Distributor_name: DIGIKEY; Distributor_part_number: 296-19100-1-ND; Height: 1.20MM; Mfr_name: TEXAS INSTRUMENTS; Mistral Part No: 143009060004-R; Package: TSSOP24; Part_type: ICS\TELECOM\TRANSCEIVER; Project: STORM2; RoHS: RoHS; Temperature: -40°C+85°C; Tolerance: NA; Voltage: NA; Wattage: NA; Weight: 89.5mg; Datasheet: Y:\MIS_DATABASE\DATASHEETS\ICS\DIGITAL\BUSTRANSCEIVER\SN74AVC8T245.PDF
U45 = DIR9001PW_TSSOP28_TI: IC 24-BIT AUDIO INTERFACE RECEIVER TSSOP28; Chkd/date: NAVEED/240315; Crtd /date: VASANTHA/250914; Custom_Duty: 15%; Customs_HS_Code: 85423100; Distributor_name: DIGIKEY; Distributor_part_number: 296-21389-5-ND; Footprint Path: Y:\MIS_DATABASE\Library\ALTIUM_TOOL\PCB_FOOTPRINTS\Altium_Footprint_Lib.PcbLib; Height: 1.20MM; Library Path: Y:\MIS_DATABASE\Library\ALTIUM_TOOL\SCHEMATICS_PARTS\MS_BUSDRIVERTRANSCEIVER_Library.schlib; Library Ref: DIR9001PW_TSSOP28; Mfr_name: TEXAS INSTRUMENTS; Mistral Part No: 141014090026-R; Package: TSSOP28; Part_type: ICS\DIGITAL\BUSTRANSCEIVER; Project: GALILEO_EVM; RoHS: RoHS; Temperature: -40°C+85°C; Tolerance: NA; Voltage: NA; Wattage: NA; Weight: NA; Datasheet: Y:\MIS_DATABASE\DATASHEETS\ICS\DIGITAL\BUSTRANSCEIVER\DIR9001.PDF
Y1 = CRY: CRY 24.576MHz 18pF SMD; Chkd/date: MANIRAJA/041018; Crtd /date: MUDDU/190710; Custom_Duty: 24%; Customs_HS_Code: 85439000; Distributor_name: DIGIKEY; Distributor_part_number: XC1703CT-ND; Footprint Path: Y:\MIS_DATABASE\Library\ALTIUM_TOOL\PCB_FOOTPRINTS\Altium_Footprint_Lib.PcbLib; Height: 4.30MM; Library Path: Y:\MIS_DATABASE\Library\ALTIUM_TOOL\SCHEMATICS_PARTS\MS_DISCRETE_Library.schlib; Mfr_name: ECS INC; Mfr_part_number: ECS-245.7-18-5PXEN-TR; Mistral Part No: 130010070011-R; Package: SMD; Part_type: CRYSTAL; Project: TTCU; RoHS: RoHS; Temperature: -40°C+85°C; Tolerance: NA; Voltage: NA; Wattage: NA; Weight: NA; Datasheet: Y:\MIS_DATABASE\DATASHEETS\MISC\CRY_OSC\CSM-7X.PDF

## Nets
DGND: C48.2 C49.2 C54.2 C267.2 C268.2 C269.2 C270.2 C271.2 C272.2 C273.2 C276.2 C277.2 C278.2 C346.2 C348.1 J14.2 J14.4 J14.10 J14.19 J14.20 J14.29 J14.30 J14.39 J14.40 J14.41(GND1) J14.42(GND2) J14.43(GND3) J14.44(GND4) J17.26 J17.27 J17.77 J17.78 J17.115 J17.116 J17.121 J17.122 J17.123 J17.124 J17.125 J17.126 J17.127 J17.128 J17.129 J17.130 J17.131 J17.132 J20.19 J20.20 J20.41(GND1) J20.42(GND2) J20.43(GND3) J20.44(GND4) Q1.2(SOURCE) Q2.2(SOURCE) Q3.2(SOURCE) R96.1 R97.1 R98.1 R120.1 R297.2 R351.1 R361.2 R365.1 R366.1 R486.2 U14.11(GND1) U14.12(GND2) U14.13(GND3) U14.16(B6) U14.19(B3) U14.22(~{OE}) U45.6(DGND) U45.23(AGND) ; also on sheet 5 6 7 8 9 10 11 12 13 14 15 16 17 20 21 22 23 25
VCC_3V3: C48.1 C49.1 C54.1 C268.1 C269.1 C271.1 C273.1 FL25.1 R298.1 R310.1 R350.1 R352.2 R357.2 R358.1 R360.2 R363.2 R364.2 R367.1 R473.1 U14.1(VCCA) U14.23(VCCB1) U14.24(VCCB2) U45.5(VDD) ; also on sheet 5 14 15 16 17 20 21 22 23 25
VCC_12V: C346.1 C348.2 J17.49 J17.50 J17.51 J17.52 J17.53 J17.54 ; also on sheet 5 16 20
VCC_DIR: C270.1 C272.1 FL25.2 U45.24(VCC)
APP_BD_PORz: J17.76 R486.1
AUD_REFCLK1_BUF: R122.2 U14.4(A2)
AUDIO_EXT_REFCLK1: R122.1 ; also on sheet 5
DIR_AUDIO#: Q1.1(GATE) U45.1(~{AUDIO})
DIR_BCKO: U14.17(B5) U14.18(B4) U45.11(BCKO)
DIR_BFRAME: TP47.1(TP) U45.18(BFRAME)
DIR_CKSEL: R351.2 R352.1 R355.2 U45.28(CKSEL) ; also on sheet 5
DIR_CLKST: TP48.1(TP) U45.9(CLKST)
DIR_COUT: TP50.1(TP) U45.15(COUT)
DIR_DOUT: U14.21(B1) U45.12(DOUT)
DIR_EMPH: Q3.1(GATE) U45.17(EMPH)
DIR_ERROR: Q2.1(GATE) R355.1 U45.27(ERROR)
DIR_FILT: C277.1 R101.1 U45.22(FILT)
DIR_FMT0: R97.2 R360.1 U45.25(FMT0) ; also on sheet 5
DIR_FMT1: R96.2 R357.1 U45.26(FMT1) ; also on sheet 5
DIR_LRCKO: U14.14(B8) U14.15(B7) U45.10(LRCKO)
DIR_PSCK0: R363.1 R365.2 U45.13(PSCK0) ; also on sheet 5
DIR_PSCK1: R364.1 R366.2 U45.14(PSCK1) ; also on sheet 5
DIR_RESETn: R98.2 U45.21(~{RST}) ; also on sheet 5
DIR_RSV: R361.1 U45.19(RSV)
DIR_RXIN: U45.20(RXIN) ; also on sheet 25
DIR_SCKO: U14.20(B2) U45.4(SCKO)
DIR_UOUT: TP49.1(TP) U45.16(UOUT)
DIR_XTI: C276.1 U45.8(XTI) Y1.1
DIR_XTO: R359.1 U45.7(XTO)
EXP_DC_3V3: J17.57 J17.58 J17.59 J17.60 R473.2 R475.2
EXP_I2C1_SCL: J17.30 R218.2
EXP_I2C1_SDA: J17.28 R216.2
EXP_I2C2_SCL: J20.22 R310.2
EXP_I2C2_SDA: J20.21 R298.2
EXP_I2C4_SCL: J14.11 R434.2
EXP_I2C4_SDA: J14.12 R446.2
FSOUT0: TP42.1(TP) U45.2(FSOUT0)
FSOUT1: TP43.1(TP) U45.3(FSOUT1)
I2C3_SCL: R434.1 ; also on sheet 5 20 22 23
I2C3_SDA: R446.1 ; also on sheet 5 20 22 23
JAMR3_GPIO0: J14.33 ; also on sheet 5
JAMR3_GPIO1: J14.34 ; also on sheet 5
JAMR3_GPIO2: J14.35 ; also on sheet 5
JAMR3_I2S_CLK: J17.104 TP148.1(TP) ; also on sheet 14
JAMR3_I2S_DA: J17.103 TP150.1(TP) ; also on sheet 14
JAMR3_I2S_DB: J17.105 TP151.1(TP) ; also on sheet 5
JAMR3_I2S_WC: J17.102 TP149.1(TP) ; also on sheet 14
JAMR3_PWR_CTRL: R475.1 ; also on sheet 5
JAMR3_RESETn: J20.13 R297.1 ; also on sheet 5
McASP6_ACLKR: R124.1 ; also on sheet 5
McASP6_ACLKX: R123.1 ; also on sheet 14
McASP6_AFSR: R126.1 ; also on sheet 5
McASP6_AFSX: R125.1 ; also on sheet 14
McASP6_AXR0: R121.1 ; also on sheet 14
McASP11_ACLKX: R235.2 TP143.1(TP) ; also on sheet 5
McASP11_AFSX: R233.2 TP144.1(TP) ; also on sheet 5
McASP11_AXR0: J17.37 TP145.1(TP) ; also on sheet 5
McASP11_AXR1: J17.33 TP146.1(TP) ; also on sheet 5
McASP11_AXR2: J17.39 TP147.1(TP) ; also on sheet 5
McASP11_AXR3: J17.35 ; also on sheet 5
McASP11_AXR4: J17.23 ; also on sheet 5
McASP11_AXR5: J17.24 ; also on sheet 5
McASP11_AXR6: J17.22 ; also on sheet 5
McASP11_AXR7: J17.38 ; also on sheet 5
McASP_ACLKR_BUF: R124.2 U14.7(A5)
McASP_ACLKX_BUF: R123.2 U14.6(A4)
McASP_AFSR_BUF: R126.2 U14.10(A8)
McASP_AFSX_BUF: R125.2 U14.9(A7)
McASP_AXR0_BUF: R121.2 U14.3(A1)
R_DIR_XTO: C267.1 R359.2 Y1.2
WKUP_I2C0_SCL: R218.1 ; also on sheet 5
WKUP_I2C0_SDA: R216.1 ; also on sheet 5
N23684707: C278.1 R101.2
N23911217: J17.31 R233.1
N23911219: J17.29 R235.1
N24736802: R120.2 U14.2(DIR)
N24987908: LD2.2 R358.2
N24987961: LD2.1 Q2.3(DRAIN)
N24990777: LD3.2 R367.2
N24990859: LD3.1 Q3.3(DRAIN)
N24990930: LD1.2 R350.2
N24990935: LD1.1 Q1.3(DRAIN)

Not connected (* = marked no-connect by the designer): J14 1* 3* 5* 6* 7* 8* 9* 13* 14* 15* 16* 17* 18* 21* 22* 23* 24* 25* 26* 27* 28* 31* 32* 36* 37* 38*; J17 1* 2* 3* 4* 5* 6* 7* 8* 9* 10* 11* 12* 13* 14* 15* 16* 17* 18* 19* 20* 21* 25* 32* 34* 36* 40* 41* 42* 43* 44* 45* 46* 47* 48* 55* 56* 61* 62* 63* 64* 65* 66* 67* 68* 69* 70* 71* 72* 73* 74* 75* 79* 80* 81* 82* 83* 84* 85* 86* 87* 88* 89* 90* 91* 92* 93* 94* 95* 96* 97* 98* 99* 100* 101* 106* 107* 108* 109* 110* 111* 112* 113* 114* 117* 118* 119* 120*; J20 1* 2* 3* 4* 5* 6* 7* 8* 9* 10* 11* 12* 14* 15* 16* 17* 18* 23* 24* 25* 26* 27* 28* 29* 30* 31* 32* 33* 34* 35* 36* 37* 38* 39* 40*; U14 5(A3)* 8(A6)*

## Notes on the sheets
sheet 18
- JAMR3/TUNER INTERFACE
- [I2C4_SCL]
- [I2C4_SDA]
- Silkscreen "JAMR3/TUNER INTERFACE"
- [GPIO0_65]
- [GPIO0_66]
- [GPIO0_67]
- [MCASP_D6]
- [MCASP_D5]
- [MCASP_D4]
- [I2C1_SDA]
- [I2C1_SCL]
- [MCASP_CLKX]
- To Expansion
  Connector
- [MCASP_D1]
- [MCASP_FSX]
- To Expansion Connector
- [MCASP_D3]
- [MCASP_D7]
- [MCASP_D0]
- [MCASP_D2]
- Note: Supply is used to enable regulators on expansion board.  Requires to
  always be enabled (powered) for connected interfaces to function.
- [EXP_DC_3V3]
- [EXP_DC_3V3]
- PCB Note: Place C16 and C17 near to EXP_CONN connector.
- Note: Net APP_BD_PORz is pulled low
  to hold un-used periphers in reset.
- IO Expander
- Note:  Unused I2C bus is pulled to valid level.
sheet 19
- Digital Audio Interface Receiver (DIR)
- To Exp
  Conn/Mux
- From GPIO
  Expansion
- DIR Clock Selection
- DIR Format Selection
- DIR System Clock Frequency Selection
- DIR Operation Mode and Clock Source
- SERIAL AUDIO DATA OUTPUT FORMAT SELECTION
- SYSTEM CLK FREQUENCY OF PLL SELECTION
- OUTPUT CLOCK FROM
  PLL  SOURCE
- FMT[1:0] SETTING
- DOUT SERIAL AUDIO DATA
     OUTPUT FORMAT
- PSCK[1:0] SETTING
- OPERATION
    MODE
- CKSEL
- ERROR Pin
   Status
- SCKO, BCKO, LRCKO
  CLOCK SOURCE
- FMT1
- FMT0
- PSCK1
- PSCK0
- SCKO
- BCKO
- LRCKO
- H
- PLL (VCO) free-running Clock
- PLL
- L
- L
- L
- 16-bit, MSB-first, Right-justified
- L
- L
- 128 fs
- 64 fs
- fs
- (default)
- L
- PLL recovered clock
- H
- XTAL clock
- L
- H
- 24-bit, MSB-first, Right-justified
- L
- H
- 256 fs
- 64 fs
- fs
- XTAL
- H
- L
- XTAL clock
- H
- L
- 24-bit, MSB-first, Left-justified
- H
- L
- 384 fs
- 64 fs
- fs
- H
- XTAL clock
- AUTO
- Connected to
   ERROR Pin
- L
- PLL recovered clock
- (default)
- H
- H
- 24-bit, MSB-first, I2S
- (default)
- H
- H
- 512 fs
- 64 fs
- fs
